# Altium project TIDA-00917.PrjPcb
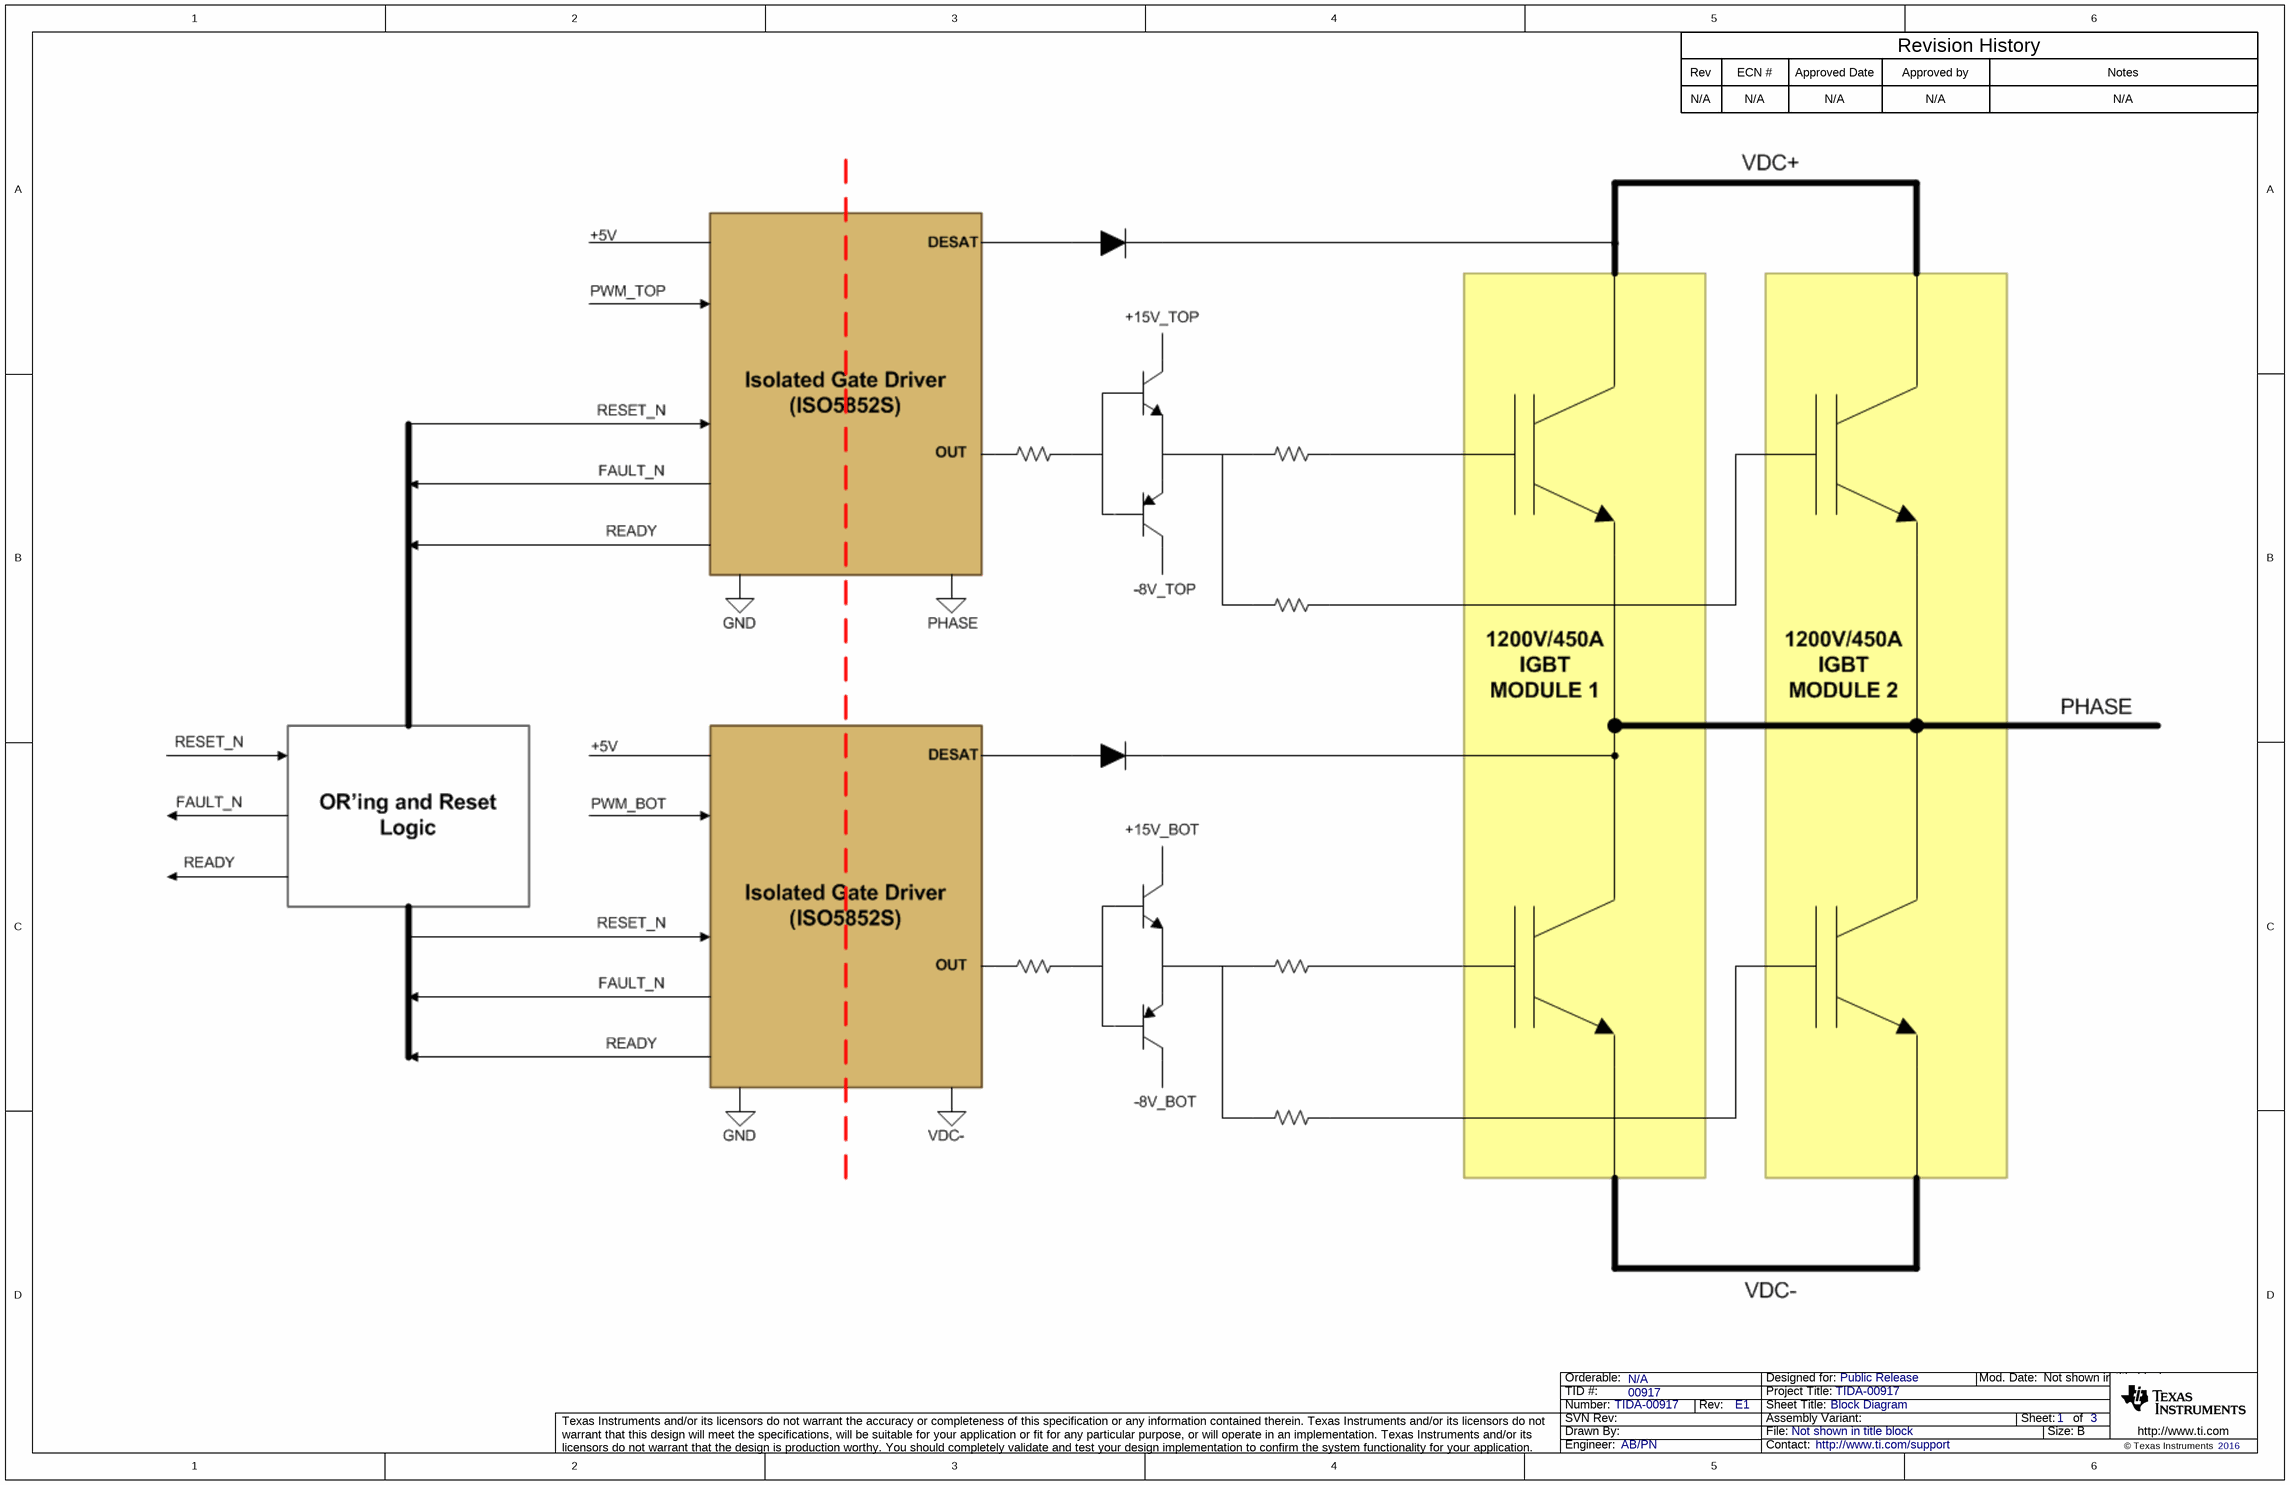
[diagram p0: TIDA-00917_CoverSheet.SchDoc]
TID: 00917; TechSupport: http://www.ti.com/support; SCH_Rev: E1; PRJ_Title: TIDA-00917; PRJ_Number: TIDA-00917; PRJ_Engineer: AB/PN; PRJ_Customer: Public Release; PCB_Rev: E1; PCB_Layout: Avinash N; EVM_orderable: N/A; CopyrightYear: 2016
3 sheets, 135 parts. Net scope: global (net labels, ports and power ports of the same name join across sheets).
Board file: TIDA-00917.PcbDoc
Sheets:
  TIDA-00917_CoverSheet.SchDoc
  TIDA-00917_BlankSheet.SchDoc
  TIDA-00917_EVM_Hardware.SchDoc

## Sheet TIDA-00917_CoverSheet.SchDoc: Block Diagram
size 431 x 279 mm; Date: Not shown in title block; ApprovedBy: Not shown in title block; CheckedBy: Not shown in title block; Author: Not shown in title block; CompanyName: Not shown in title block; Engineer: Not shown in title block; Organization: Not shown in title block; Address1: Not shown in title block; Address2: Not shown in title block; Address3: Not shown in title block; Address4: Not shown in title block; DocumentNumber: 1; Revision: Use project parameter SCH_Rev; SheetNumber: 1; SheetTotal: 3; PageSetup: Record=PageOptions¦CenterHorizontal=True¦CenterVertical=True¦PrintScale=1.00¦XCorrection=1.00¦YCorrection=1.00¦PrintKind=0¦BorderSize=5000000¦LeftOffset=0¦BottomOffset=0¦Orientation=2¦PaperLength=1000¦PaperWidth=1000¦Scale=100¦PaperSource=15¦PrintQuality=600¦MediaType=1¦DitherType=10¦PaperKind=Letter¦PrintScaleMode=1

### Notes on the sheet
- Rev
- N/A
- ECN #
- Approved Date
- Approved by
- Revision History
- Notes

## Sheet TIDA-00917_BlankSheet.SchDoc: IGBT Gate Drive
size 431 x 279 mm; Date: Not shown in title block; ApprovedBy: Not shown in title block; CheckedBy: Not shown in title block; Author: Not shown in title block; CompanyName: Not shown in title block; Engineer: Not shown in title block; Organization: Not shown in title block; Address1: Not shown in title block; Address2: Not shown in title block; Address3: Not shown in title block; Address4: Not shown in title block; DocumentNumber: 1; Revision: Use project parameter SCH_Rev; SheetNumber: 2; SheetTotal: 3; PageSetup: Record=PageOptions¦CenterHorizontal=True¦CenterVertical=True¦PrintScale=1.00¦XCorrection=1.00¦YCorrection=1.00¦PrintKind=0¦BorderSize=5000000¦LeftOffset=0¦BottomOffset=0¦Orientation=2¦PaperLength=1000¦PaperWidth=1000¦Scale=100¦PaperSource=15¦PrintQuality=600¦MediaType=1¦DitherType=10¦PrintScaleMode=1¦PaperKind=Letter
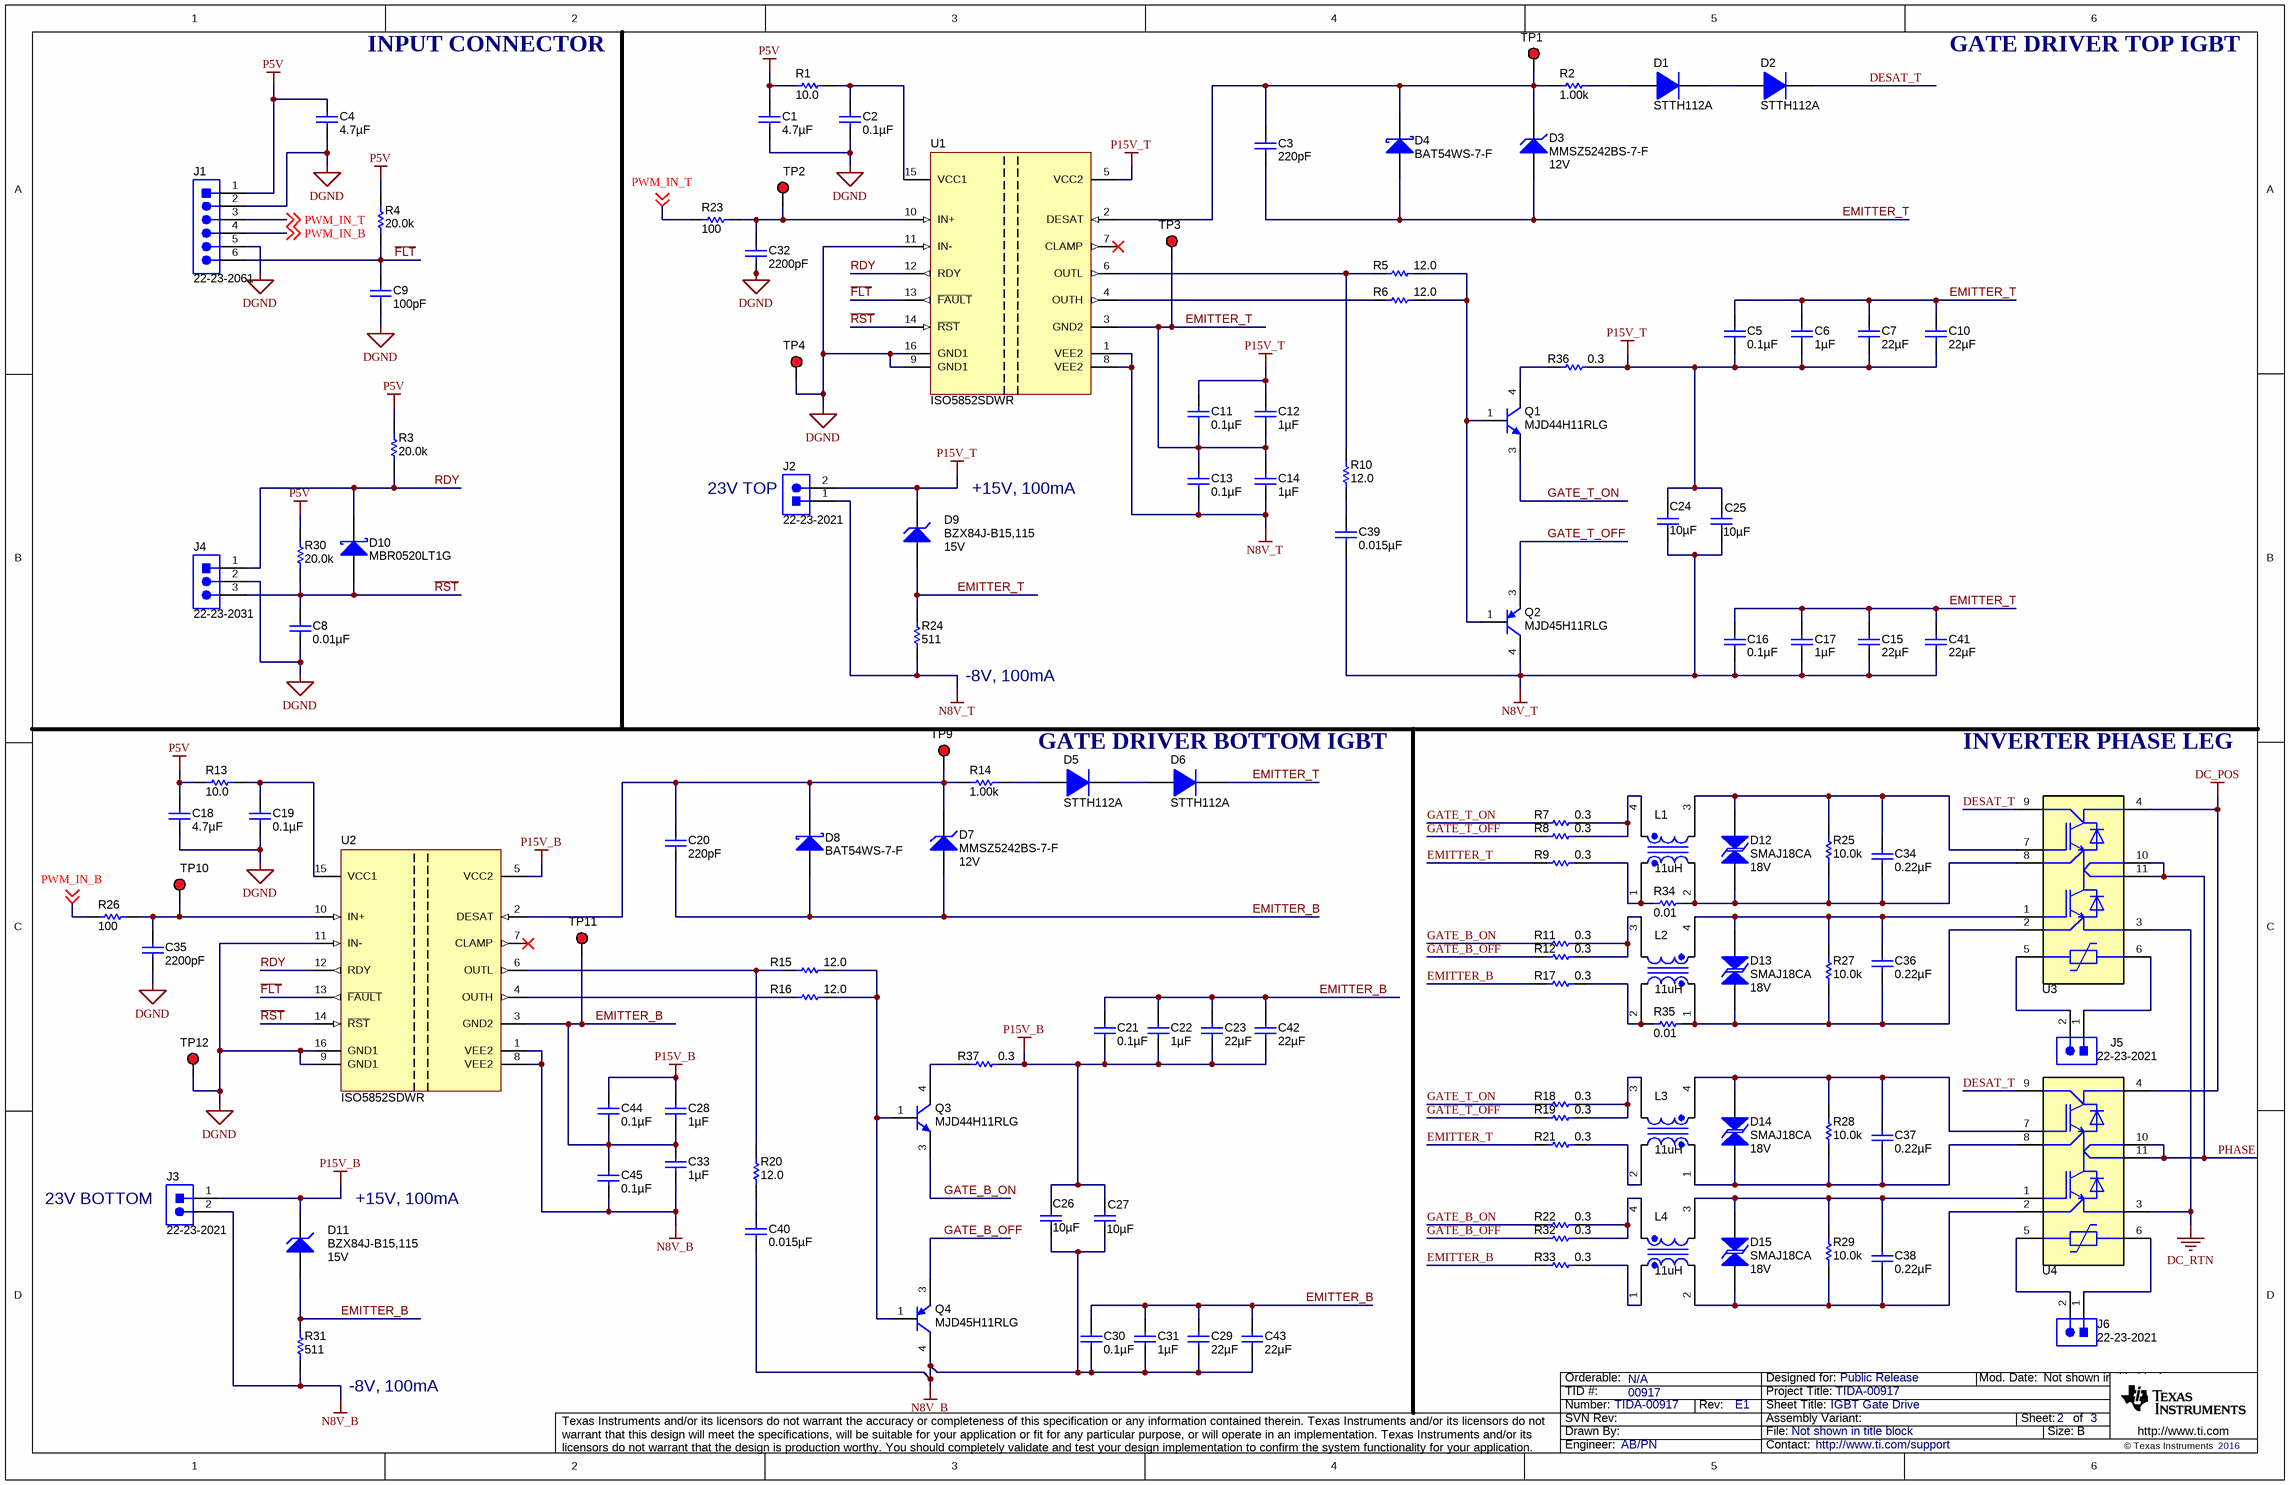
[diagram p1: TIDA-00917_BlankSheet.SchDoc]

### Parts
C1  ValueDisplayed: 4.7µF  [0805_HV]  (hidden comment: GRM21BR71C475KA73L)
C2  ValueDisplayed: 0.1µF  [0603]  (hidden comment: C1608X7R1H104K080AA)
C3  ValueDisplayed: 220pF  [0603]  (hidden comment: C0603C221K5RACTU)
C4  ValueDisplayed: 4.7µF  [0805_HV]  (hidden comment: GRM21BR71C475KA73L)
C5  ValueDisplayed: 0.1µF  [0603]  (hidden comment: C1608X7R1H104K080AA)
C6  ValueDisplayed: 1µF  [0805_HV]  (hidden comment: CL21B105KBFNNNE)
C7  ValueDisplayed: 22µF  [1210_270]  (hidden comment: GRM32ER71E226KE15L)
C8  ValueDisplayed: 0.01µF  [0402]  (hidden comment: GRM155R71C103KA01D)
C9  ValueDisplayed: 100pF  [0402]  (hidden comment: C0402C101J3GACTU)
C10  ValueDisplayed: 22µF  [1210_270]  (hidden comment: GRM32ER71E226KE15L)
C11  ValueDisplayed: 0.1µF  [0603]  (hidden comment: C1608X7R1H104K080AA)
C12  ValueDisplayed: 1µF  [1206]  (hidden comment: C3216X7R2A105M160AA)
C13  ValueDisplayed: 0.1µF  [0603]  (hidden comment: C1608X7R1H104K080AA)
C14  ValueDisplayed: 1µF  [1206]  (hidden comment: C3216X7R2A105M160AA)
C15  ValueDisplayed: 22µF  [1210_270]  (hidden comment: GRM32ER71E226KE15L)
C16  ValueDisplayed: 0.1µF  [0603]  (hidden comment: C1608X7R1H104K080AA)
C17  ValueDisplayed: 1µF  [0805_HV]  (hidden comment: CL21B105KBFNNNE)
C18  ValueDisplayed: 4.7µF  [0805_HV]  (hidden comment: GRM21BR71C475KA73L)
C19  ValueDisplayed: 0.1µF  [0603]  (hidden comment: C1608X7R1H104K080AA)
C20  ValueDisplayed: 220pF  [0603]  (hidden comment: C0603C221K5RACTU)
C21  ValueDisplayed: 0.1µF  [0603]  (hidden comment: C1608X7R1H104K080AA)
C22  ValueDisplayed: 1µF  [0805_HV]  (hidden comment: CL21B105KBFNNNE)
C23  ValueDisplayed: 22µF  [1210_270]  (hidden comment: GRM32ER71E226KE15L)
C24  ValueDisplayed: 10µF  [1210_280]  (hidden comment: UMK325AB7106KM-T)
C25  ValueDisplayed: 10µF  [1210_280]  (hidden comment: UMK325AB7106KM-T)
C26  ValueDisplayed: 10µF  [1210_280]  (hidden comment: UMK325AB7106KM-T)
C27  ValueDisplayed: 10µF  [1210_280]  (hidden comment: UMK325AB7106KM-T)
C28  ValueDisplayed: 1µF  [1206]  (hidden comment: C3216X7R2A105M160AA)
C29  ValueDisplayed: 22µF  [1210_270]  (hidden comment: GRM32ER71E226KE15L)
C30  ValueDisplayed: 0.1µF  [0603]  (hidden comment: C1608X7R1H104K080AA)
C31  ValueDisplayed: 1µF  [0805_HV]  (hidden comment: CL21B105KBFNNNE)
C32  ValueDisplayed: 2200pF  [0402]  (hidden comment: 885012205027)
C33  ValueDisplayed: 1µF  [1206]  (hidden comment: C3216X7R2A105M160AA)
C34  ValueDisplayed: 0.22µF  [0603]  (hidden comment: GRM188R71H224KAC4D)
C35  ValueDisplayed: 2200pF  [0402]  (hidden comment: 885012205027)
C36  ValueDisplayed: 0.22µF  [0603]  (hidden comment: GRM188R71H224KAC4D)
C37  ValueDisplayed: 0.22µF  [0603]  (hidden comment: GRM188R71H224KAC4D)
C38  ValueDisplayed: 0.22µF  [0603]  (hidden comment: GRM188R71H224KAC4D)
C39  ValueDisplayed: 0.015µF  [0603]  (hidden comment: C0603C153K1RACTU)
C40  ValueDisplayed: 0.015µF  [0603]  (hidden comment: C0603C153K1RACTU)
C41  ValueDisplayed: 22µF  [1210_270]  (hidden comment: GRM32ER71E226KE15L)
C42  ValueDisplayed: 22µF  [1210_270]  (hidden comment: GRM32ER71E226KE15L)
C43  ValueDisplayed: 22µF  [1210_270]  (hidden comment: GRM32ER71E226KE15L)
C44  ValueDisplayed: 0.1µF  [0603]  (hidden comment: C1608X7R1H104K080AA)
C45  ValueDisplayed: 0.1µF  [0603]  (hidden comment: C1608X7R1H104K080AA)
D1  STTH112A  [SMA]
D2  STTH112A  [SMA]
D3  MMSZ5242BS-7-F  value 12V  [sod-323]
D4  BAT54WS-7-F  [SOD-323]
D5  STTH112A  [SMA]
D6  STTH112A  [SMA]
D7  MMSZ5242BS-7-F  value 12V  [sod-323]
D8  BAT54WS-7-F  [SOD-323]
D9  BZX84J-B15,115  Voltage - Zener (Nom) (Vz): 15V  [SOD-323F]
D10  MBR0520LT1G  [SOD-123]
D11  BZX84J-B15,115  Voltage - Zener (Nom) (Vz): 15V  [SOD-323F]
D12  SMAJ18CA  value 18V  [SMA]
D13  SMAJ18CA  value 18V  [SMA]
D14  SMAJ18CA  value 18V  [SMA]
D15  SMAJ18CA  value 18V  [SMA]
J1  22-23-2061  [Molex_22-23-2061]
J2  22-23-2021  [Molex_22-23-2021]
J3  22-23-2021  [Molex_22-23-2021]
J4  22-23-2031  [Molex_22-23-2031]
J5  22-23-2021  [Molex_22-23-2021]
J6  22-23-2021  [Molex_22-23-2021]
L1  value 11uH  [SIMDAD_1812]  (hidden comment: B82789C0113N002)
L2  value 11uH  [SIMDAD_1812]  (hidden comment: B82789C0113N002)
L3  value 11uH  [SIMDAD_1812]  (hidden comment: B82789C0113N002)
L4  value 11uH  [SIMDAD_1812]  (hidden comment: B82789C0113N002)
Q1  MJD44H11RLG  [DPAK]
Q2  MJD45H11RLG  [DPAK]
Q3  MJD44H11RLG  [DPAK]
Q4  MJD45H11RLG  [DPAK]
R1  ValueDisplayed: 10.0  [0603]  (hidden comment: CRCW060310R0FKEA)
R2  ValueDisplayed: 1.00k  [0805_HV]  (hidden comment: ERJ-6ENF1001V)
R3  ValueDisplayed: 20.0k  [0402]  (hidden comment: CRCW040220K0FKED)
R4  ValueDisplayed: 20.0k  [0402]  (hidden comment: CRCW040220K0FKED)
R5  ValueDisplayed: 12.0  [1206]  (hidden comment: RC1206FR-0712RL)
R6  ValueDisplayed: 12.0  [1206]  (hidden comment: RC1206FR-0712RL)
R7  ValueDisplayed: 0.3  [2512]  (hidden comment: CSRN2512FKR300)
R8  ValueDisplayed: 0.3  [2512]  (hidden comment: CSRN2512FKR300)
R9  ValueDisplayed: 0.3  [2512]  (hidden comment: CSRN2512FKR300)
R10  ValueDisplayed: 12.0  [1206]  (hidden comment: RC1206FR-0712RL)
R11  ValueDisplayed: 0.3  [2512]  (hidden comment: CSRN2512FKR300)
R12  ValueDisplayed: 0.3  [2512]  (hidden comment: CSRN2512FKR300)
R13  ValueDisplayed: 10.0  [0603]  (hidden comment: CRCW060310R0FKEA)
R14  ValueDisplayed: 1.00k  [0805_HV]  (hidden comment: ERJ-6ENF1001V)
R15  ValueDisplayed: 12.0  [1206]  (hidden comment: RC1206FR-0712RL)
R16  ValueDisplayed: 12.0  [1206]  (hidden comment: RC1206FR-0712RL)
R17  ValueDisplayed: 0.3  [2512]  (hidden comment: CSRN2512FKR300)
R18  ValueDisplayed: 0.3  [2512]  (hidden comment: CSRN2512FKR300)
R19  ValueDisplayed: 0.3  [2512]  (hidden comment: CSRN2512FKR300)
R20  ValueDisplayed: 12.0  [1206]  (hidden comment: RC1206FR-0712RL)
R21  ValueDisplayed: 0.3  [2512]  (hidden comment: CSRN2512FKR300)
R22  ValueDisplayed: 0.3  [2512]  (hidden comment: CSRN2512FKR300)
R23  ValueDisplayed: 100  [0402]  (hidden comment: CRCW0402100RFKED)
R24  ValueDisplayed: 511  [1206]  (hidden comment: ERJ-8ENF5110V)
R25  ValueDisplayed: 10.0k  [0603]  (hidden comment: ERJ-3EKF1002V)
R26  ValueDisplayed: 100  [0402]  (hidden comment: CRCW0402100RFKED)
R27  ValueDisplayed: 10.0k  [0603]  (hidden comment: ERJ-3EKF1002V)
R28  ValueDisplayed: 10.0k  [0603]  (hidden comment: ERJ-3EKF1002V)
R29  ValueDisplayed: 10.0k  [0603]  (hidden comment: ERJ-3EKF1002V)
R30  ValueDisplayed: 20.0k  [0402]  (hidden comment: CRCW040220K0FKED)
R31  ValueDisplayed: 511  [1206]  (hidden comment: ERJ-8ENF5110V)
R32  ValueDisplayed: 0.3  [2512]  (hidden comment: CSRN2512FKR300)
R33  ValueDisplayed: 0.3  [2512]  (hidden comment: CSRN2512FKR300)
R34  ValueDisplayed: 0.01  [1206]  (hidden comment: WSLP1206R0100FEA)
R35  ValueDisplayed: 0.01  [1206]  (hidden comment: WSLP1206R0100FEA)
R36  ValueDisplayed: 0.3  [2512]  (hidden comment: CSRN2512FKR300)
R37  ValueDisplayed: 0.3  [2512]  (hidden comment: CSRN2512FKR300)
TP1  5005  [Keystone5005]  (value not drawn)
TP2  5005  [Keystone5005]  (value not drawn)
TP3  5005  [Keystone5005]  (value not drawn)
TP4  5005  [Keystone5005]  (value not drawn)
TP9  5005  [Keystone5005]  (value not drawn)
TP10  5005  [Keystone5005]  (value not drawn)
TP11  5005  [Keystone5005]  (value not drawn)
TP12  5005  [Keystone5005]  (value not drawn)
U1  ISO5852SDWR  [DW0016B_HV]
U2  ISO5852SDWR  [DW0016B_HV]
U3  SEMIX453GB12E4P  [SEMIKRON_SEMIX453GB12E4P]  (value not drawn)
U4  SEMIX453GB12E4P  [SEMIKRON_SEMIX453GB12E4P]  (value not drawn)

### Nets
DC_POS: U3.4 U4.4
DC_RTN: U3.3 U4.3
DGND: C1.2 C2.2 C4.2 C8.2 C9.2 C18.2 C19.2 C32.2 C35.2 J1.2 J1.5 J4.2 TP4.1 TP12.1 U1.9(GND1) U1.11(IN-) U1.16(GND1) U2.9(GND1) U2.11(IN-) U2.16(GND1)
N8V_B: C26.2 C27.2 C29.2 C30.2 C31.2 C33.2 C40.2 C43.2 C45.2 J3.2 Q4.4(C) R31.1 U2.1(VEE2) U2.8(VEE2)
N8V_T: C13.2 C14.2 C15.2 C16.2 C17.2 C24.2 C25.2 C39.2 C41.2 J2.1 Q2.4(C) R24.1 U1.1(VEE2) U1.8(VEE2)
P5V: C1.1 C4.1 C18.1 J1.1 R1.1 R3.2 R4.2 R13.1 R30.2
P15V_B: C21.2 C22.2 C23.2 C26.1 C27.1 C28.1 C42.2 C44.1 D11.1(K) J3.1 R37.2 U2.5(VCC2)
P15V_T: C5.2 C6.2 C7.2 C10.2 C11.1 C12.1 C24.1 C25.1 D9.1(K) J2.2 R36.2 U1.5(VCC2)
~{FLT}: C9.1 J1.6 R4.1 U1.13(~{FAULT}) U2.13(~{FAULT})
~{RST}: C8.1 D10.2(A) J4.3 R30.1 U1.14(~{RST}) U2.14(~{RST})
DESAT_T: D2.1(K) U3.9 U4.9
EMITTER_B: C20.2 C21.1 C22.1 C23.1 C28.2 C29.1 C30.1 C31.1 C33.1 C42.1 C43.1 C44.2 C45.1 D7.2(A) D8.2(A) D11.2(A) R17.1 R31.2 R33.1 TP11.1 U2.3(GND2)
EMITTER_T: C3.2 C5.1 C6.1 C7.1 C10.1 C11.2 C12.2 C13.1 C14.1 C15.1 C16.1 C17.1 C41.1 D3.2(A) D4.2(A) D6.1(K) D9.2(A) R9.1 R21.1 R24.2 TP3.1 U1.3(GND2)
GATE_B_OFF: Q4.3(E) R12.1 R32.1
GATE_B_ON: Q3.3(E) R11.1 R22.1
GATE_T_OFF: Q2.3(E) R8.1 R19.1
GATE_T_ON: Q1.3(E) R7.1 R18.1
PHASE: U3.10 U3.11 U4.10 U4.11
PWM_IN_B: J1.4 R26.1 ; off-sheet PWM_IN_B
PWM_IN_T: J1.3 R23.1 ; off-sheet PWM_IN_T
RDY: D10.1(K) J4.1 R3.1 U1.12(RDY) U2.12(RDY)
NetC2_1: C2.1 R1.2 U1.15(VCC1)
NetC3_1: C3.1 D3.1(K) D4.1(K) R2.1 TP1.1 U1.2(DESAT)
NetC19_1: C19.1 R13.2 U2.15(VCC1)
NetC20_1: C20.1 D7.1(K) D8.1(K) R14.1 TP9.1 U2.2(DESAT)
NetC32_1: C32.1 R23.2 TP2.1 U1.10(IN+)
NetC34_1: C34.1 D12.2 L1.3 R25.2 U3.7
NetC34_2: C34.2 D12.1 L1.2 R25.1 R34.2 U3.8
NetC35_1: C35.1 R26.2 TP10.1 U2.10(IN+)
NetC36_1: C36.1 D13.2 L2.4 R27.2 U3.1
NetC36_2: C36.2 D13.1 L2.1 R27.1 R35.2 U3.2
NetC37_1: C37.1 D14.2 L3.4 R28.2 U4.7
NetC37_2: C37.2 D14.1 L3.1 R28.1 U4.8
NetC38_1: C38.1 D15.2 L4.3 R29.2 U4.1
NetC38_2: C38.2 D15.1 L4.2 R29.1 U4.2
NetC39_1: C39.1 R10.1
NetC40_1: C40.1 R20.1
NetD1_1: D1.1(K) D2.2(A)
NetD1_2: D1.2(A) R2.2
NetD5_1: D5.1(K) D6.2(A)
NetD5_2: D5.2(A) R14.2
NetJ5_1: J5.1 U3.6
NetJ5_2: J5.2 U3.5
NetJ6_1: J6.1 U4.6
NetJ6_2: J6.2 U4.5
NetL1_1: L1.1 R9.2 R34.1
NetL1_4: L1.4 R7.2 R8.2
NetL2_2: L2.2 R17.2 R35.1
NetL2_3: L2.3 R11.2 R12.2
NetL3_2: L3.2 R21.2
NetL3_3: L3.3 R18.2 R19.2
NetL4_1: L4.1 R33.2
NetL4_4: L4.4 R22.2 R32.2
NetQ1_1: Q1.1(B) Q2.1(B) R5.2 R6.2
NetQ1_4: Q1.4(C) R36.1
NetQ3_1: Q3.1(B) Q4.1(B) R15.2 R16.2
NetQ3_4: Q3.4(C) R37.1
NetR5_1: R5.1 R10.2 U1.6(OUTL)
NetR6_1: R6.1 U1.4(OUTH)
NetR15_1: R15.1 R20.2 U2.6(OUTL)
NetR16_1: R16.1 U2.4(OUTH)

Not connected (* = marked no-connect by the designer): U1 7(CLAMP)*; U2 7(CLAMP)*

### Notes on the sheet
- INPUT CONNECTOR
- GATE DRIVER TOP IGBT
- (near J2) 23V TOP
- +15V, 100mA
- -8V, 100mA
- GATE DRIVER BOTTOM IGBT
- INVERTER PHASE LEG
- (near J3) 23V BOTTOM

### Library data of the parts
C1 C4 C18 = GRM21BR71C475KA73L: CAP, CERM, 4.7 µF, 16 V, +/- 10%, X7R, 0805; Manufacturer: MuRata; Polarized: N; CompType: Capacitor; Value: 4.7uF; U/M: EA; Cap_F: 0.0000047; Tolerance_%: 10; ESR_ohm: 0.006; Value1: 0.006 ohm; VDC_V: 16; Value2: 16V; TaMin_C: -55; TaMax_C: 125; Cap_Case: 0805; SizeArea_mm2: 2.5; SizeAreaWB_mm2: 6.75; SizeX_mm: 2; SizeY_mm: 1.25; SizeZ_mm: 1.45; AEC Category: Q200
C2 C5 C16 C19 C21 C30 = C1608X7R1H104K080AA: CAP, CERM, 0.1 µF, 50 V, +/- 10%, X7R, 0603; Manufacturer: TDK; Polarized: N; CompType: Capacitor; Value: 0.1uF; U/M: EA; Cap_F: 0.0000001; Tolerance_%: 10; Value1: Unknown; VDC_V: 50; Value2: 50V; TaMin_C: -55; TaMax_C: 125; AEC Category: Q200
C3 C20 = C0603C221K5RACTU: CAP, CERM, 220 pF, 50 V, +/- 10%, X7R, 0603; Manufacturer: Kemet; Polarized: N; CompType: Capacitor; Value: 220pF; U/M: EA; Cap_F: 0.00000000022; Tolerance_%: 10; Value1: Unknown; VDC_V: 50; Value2: 50V; TaMin_C: -55; TaMax_C: 125; AEC Category: Q200
C6 C17 C22 C31 = CL21B105KBFNNNE: CAP, CERM, 1 µF, 50 V, +/- 10%, X7R, 0805; Manufacturer: Samsung Electro-Mechanics; Polarized: N; CompType: Capacitor; Value: 1uF; U/M: EA; Cap_F: 0.000001; Tolerance_%: 10; Value1: Unknown; VDC_V: 50; Value2: 50V; TaMin_C: -55; TaMax_C: 125; Cap_Case: 0805; AEC Category: Q200
C7 C10 C15 C23 C29 C41-C43 = GRM32ER71E226KE15L: CAP, CERM, 22 µF, 25 V, +/- 10%, X7R, 1210; Manufacturer: MuRata; Polarized: N; CompType: Capacitor; Value: 22uF; U/M: EA; Cap_F: 0.000022; Tolerance_%: 10; Value1: Unknown; VDC_V: 25; Value2: 25V; TaMin_C: -55; TaMax_C: 125; Cap_Case: 1210; SizeArea_mm2: 8; SizeAreaWB_mm2: 14.7; SizeX_mm: 3.2; SizeY_mm: 2.5; SizeZ_mm: 2.7; AEC Category: Q200
C8 = GRM155R71C103KA01D: CAP, CERM, 0.01 µF, 16 V, +/- 10%, X7R, 0402; Manufacturer: MuRata; Polarized: N; CompType: Capacitor; Value: 0.01uF; U/M: EA; Cap_F: 0.00000001; Tolerance_%: 10; Value1: Unknown; VDC_V: 16; Value2: 16V; TaMin_C: -55; TaMax_C: 125; SizeArea_mm2: 0.5; SizeAreaWB_mm2: 3; SizeX_mm: 1; SizeZ_mm: 0.6; AEC Category: Q200
C9 = C0402C101J3GACTU: CAP, CERM, 100 pF, 25 V, +/- 5%, C0G/NP0, 0402; Manufacturer: Kemet; Polarized: N; CompType: Capacitor; Value: 100pF; U/M: EA; Cap_F: 0.0000000001; Tolerance_%: 5; Value1: Unknown; VDC_V: 25; Value2: 25V; TaMin_C: -55; TaMax_C: 125; SizeArea_mm2: 0.5; SizeAreaWB_mm2: 3; SizeX_mm: 1; SizeZ_mm: 0.6; AEC Category: Q200
C11 C13 C44 C45 = C1608X7R1H104K080AA: CAP, CERM, 0.1 µF, 50 V, +/- 10%, X7R, 0603; Manufacturer: TDK; Polarized: N; CompType: Capacitor; Value: 0.1uF; U/M: EA; Cap_F: 0.0000001; Tolerance_%: 10; ESR_ohm: 0.0296; Value1: 0.0296 ohm; VDC_V: 50; Value2: 50V; IRMS_A: 0.97199; TaMin_C: -55; TaMax_C: 125; SizeArea_mm2: 1.28; SizeAreaWB_mm2: 4.68; SizeX_mm: 1.6; SizeY_mm: 0.8; SizeZ_mm: 1; AEC Category: Q200
C12 C14 C28 C33 = C3216X7R2A105M160AA: CAP, CERM, 1 µF, 100 V, +/- 20%, X7R, 1206; Manufacturer: TDK; Polarized: N; CompType: Capacitor; Value: 1uF; U/M: EA; Cap_F: 0.000001; Tolerance_%: 20; Value1: Unknown; VDC_V: 100; Value2: 100V; TaMin_C: -55; TaMax_C: 125; SizeArea_mm2: 5.12; SizeAreaWB_mm2: 10.92; SizeX_mm: 3.2; SizeY_mm: 1.6; SizeZ_mm: 1.35; AEC Category: Q200
C24-C27 = UMK325AB7106KM-T: CAP, CERM, 10 µF, 50 V, +/- 10%, X7R, 1210; Manufacturer: Taiyo Yuden; Polarized: N; CompType: Capacitor; Value: 10uF; U/M: EA; Cap_F: 0.00001; Tolerance_%: 10; Value1: Unknown; VDC_V: 50; Value2: 50V; TaMin_C: -55; TaMax_C: 125; Cap_Case: 1210; SizeArea_mm2: 8; SizeAreaWB_mm2: 14.7; SizeX_mm: 3.2; SizeY_mm: 2.5; SizeZ_mm: 2.8; AEC Category: Q200
C32 C35 = 885012205027: CAP, CERM, 2200 pF, 16 V, +/- 10%, X7R, 0402; Manufacturer: Wurth Elektronik; Polarized: N; CompType: Capacitor; Value: 2200pF; U/M: EA; Cap_F: 0.0000000022; Tolerance_%: 10; Value1: Unknown; VDC_V: 16; Value2: 16V; TaMin_C: -55; TaMax_C: 125; SizeArea_mm2: 0.5; SizeAreaWB_mm2: 3; SizeX_mm: 1; SizeZ_mm: 0.6; AEC Category: Q200
C34 C36-C38 = GRM188R71H224KAC4D: CAP, CERM, 0.22 µF, 50 V, +/- 10%, X7R, 0603; Manufacturer: MuRata; Polarized: N; CompType: Capacitor; Value: 0.22uF; U/M: EA; Cap_F: 0.00000022; Tolerance_%: 10; Value1: Unknown; VDC_V: 50; Value2: 50V; TaMin_C: -55; TaMax_C: 125; SizeArea_mm2: 1.28; SizeAreaWB_mm2: 4.68; SizeX_mm: 1.6; SizeY_mm: 0.8; SizeZ_mm: 1; AEC Category: Q200
C39 C40 = C0603C153K1RACTU: CAP, CERM, 0.015 µF, 100 V, +/- 10%, X7R, 0603; Manufacturer: Kemet; Polarized: N; CompType: Capacitor; Value: 0.015uF; U/M: EA; Cap_F: 0.000000015; Tolerance_%: 10; Value1: Unknown; VDC_V: 100; Value2: 100V; TaMin_C: -55; TaMax_C: 125; SizeArea_mm2: 1.28; SizeAreaWB_mm2: 4.68; SizeX_mm: 1.6; SizeY_mm: 0.8; SizeZ_mm: 1; AEC Category: Q200
D1 D2 D5 D6 = STTH112A: Diode, Ultrafast, 1200 V, 1 A, SMA; Manufacturer: STMicroelectronics; U/M: EA; Vf_V: 1.9; Value: 1200V; Value1: 1A; Value2: 1.9V; Io_A: 1; Vr_V: 1200; TJmax_C: 175; SizeAreaWB_mm2: 37.3428; SizeArea_mm2: 16.3228; SizeX_mm: 5.59; SizeY_mm: 2.92; SizeZ_mm: 2.87; AEC Category: Q101; AEC Qualified: N
D3 D7 = MMSZ5242BS-7-F: Diode, Zener, 12 V, 200 mW, SOD-323; Manufacturer: Diodes Inc.; SymbolCreator: a0412235; U/M: EA; Power_W: 0.2; Vz_V: 12; Value1: 0.2W; RJA_CperW: 350; AEC Category: Q101
D4 D8 = BAT54WS-7-F: Diode, Schottky, 30 V, 0.2 A, SOD-323; Manufacturer: Diodes Inc.; U/M: EA; Vf_V: 0.7; Value: 30V; Value1: 0.2A; Value2: 0.7V; Io_A: 0.2; Vr_V: 30; TJmax_C: 125; SizeAreaWB_mm2: 8.695; SizeArea_mm2: 3.645; SizeX_mm: 2.7; SizeY_mm: 1.35; SizeZ_mm: 1; AEC Category: Q101
D9 D11 = BZX100A, 115: DIODE ZENER 15V 550MW SOD323F; Manufacturer: NXP Semiconductors; Tolerance_%: ±2%; Impedance (Max) (Zzt): 15 Ohm; Current - Reverse Leakage @ Vr: 50nA @ 10.5V; Value: 1.1V @ 100mA
D10 = MBR0520LT1G: Diode, Schottky, 20 V, 0.5 A, SOD-123; Manufacturer: ON Semiconductor; U/M: EA; Vf_V: 0.385; Value: 20V; Value1: 0.5A; Value2: 0.385V; Io_A: 0.5; Vr_V: 20; TJmax_C: 125; RJC_CperW: 150; SizeAreaWB_mm2: 13.095; SizeArea_mm2: 6.545; SizeX_mm: 3.85; SizeY_mm: 1.7; SizeZ_mm: 1.35; AEC Category: Q101
D12-D15 = SMAJ18CA: Diode, TVS, Bi, 18 V, 400 W, SMA; Manufacturer: Littelfuse; U/M: EA; Power_W: 400; Vr_V: 18; Value1: 400W; RJA_CperW: 120; SizeAreaWB_mm2: 37.3428; SizeArea_mm2: 16.3228; SizeX_mm: 5.59; SizeY_mm: 2.92; SizeZ_mm: 2.87; AEC Category: Q101
J1 = 22-23-2061: Header, 2.54 mm, 6x1, Tin, TH; Manufacturer: Molex; SymbolCreator: a0412235; Pitch_mm: 2.54; Gender: Male; Shrouded: N; Row_Count: 1
J2 J3 J5 J6 = 22-23-2021: Header, 2.54mm, 2x1, Vertical, TH; Manufacturer: Molex; SymbolCreator: a0412235
J4 = 22-23-2031: Header, 2.54 mm, 3x1, Tin, TH; Manufacturer: Molex; SymbolCreator: a0799628; Pitch_mm: 2.54; Gender: Male; Shrouded: N; Row_Count: 1
L1-L4 = B82789C0104H001: Coupled inductor, 11 µH, 0.3 A, 0.25 ohm, SMD; Manufacturer: TDK; SymbolCreator: a0412235; Ind_H: 11.0E-6; DCR_ohm: 0.25
Q1 Q3 = MJD44H11RLG, ON Semiconductor: Transistor, NPN, 80 V, 8 A, AEC-Q101, DPAK; CompType: BJT; PNP: 0; NPN: 1; Vceo_V: 80; Value: 80 V; IcRated_A: 8; Value1: 8 A; TaMin_C: -55; TaMax_C: 150; U/M: EA; AEC Category: Q101; AEC Qualified: Y
Q2 Q4 = MJD45H11RLG, ON Semiconductor: Transistor, PNP, 80 V, 8 A, DPAK; CompType: BJT; PNP: 1; NPN: 0; Vceo_V: 80; Value: 80 V; IcRated_A: 8; Value1: 8 A; TaMin_C: -55; TaMax_C: 150; U/M: EA; AEC Category: Q101
R1 R13 = CRCW060310R0FKEA: RES, 10.0, 1%, 0.1 W, 0603; Manufacturer: Vishay-Dale; CompType: Resistor; Value: 10.0; Res_ohm: 10; Value_Code: 10R0; Tolerance_%: 1; Power_W: 0.1; Value2: 0.1W; VDC_V: 75; TempCo: 100 ppm/C; EIA_Code: E96; U/M: EA; AEC Category: Q200
R2 R14 = ERJ-6ENF1001V: RES, 1.00 k, 1%, 0.125 W, 0805; Manufacturer: Panasonic; CompType: Resistor; Value: 1.00k; Res_ohm: 1000; Value_Code: 1k00; Tolerance_%: 1; Power_W: 0.125; Value2: 0.125W; TempCo: 100 ppm/C; EIA_Code: E96; U/M: EA; AEC Category: Q200
R3 R4 R30 = CRCW040220K0FKED: RES, 20.0 k, 1%, 0.063 W, 0402; Manufacturer: Vishay-Dale; CompType: Resistor; Value: 20.0k; Res_ohm: 20000; Value_Code: 20k0; Tolerance_%: 1; Power_W: 0.063; Value2: 0.063W; VDC_V: 50; TempCo: 100 ppm/C; SizeArea_mm2: 0.5; SizeZ_mm: 0.6; EIA_Code: E96; U/M: EA; AEC Category: Q200
R5 R6 R10 R15 R16 R20 = RC1206FR-0712RL: RES, 12.0, 1%, 0.25 W, 1206; Manufacturer: Yageo America; CompType: Resistor; Value: 12.0; Res_ohm: 12; Value_Code: 12R0; Tolerance_%: 1; Power_W: 0.25; Value2: 0.25W; VDC_V: 200; TempCo: 100 ppm/C; SizeArea_mm2: 5.12; SizeX_mm: 3.2; SizeY_mm: 1.6; SizeZ_mm: 1.35; U/M: EA; AEC Category: Q200
R7-R9 R11 R12 R17-R19 R21 R22 R32 R33 R36 R37 = CSRN2512FKR300: RES, 0.3, 1%, 2 W, 2512; Manufacturer: Stackpole Electronics Inc; CompType: Resistor; Value: 0.3; Value_Code: R300; Tolerance_%: 1; Power_W: 2; Value2: 2W; TempCo: 200 ppm/C; SizeArea_mm2: 20.16; SizeX_mm: 6.3; SizeY_mm: 3.2; SizeZ_mm: 0.71; EIA_Code: E96; U/M: EA; AEC Category: Q200
R23 R26 = CRCW0402100RFKED: RES, 100, 1%, 0.063 W, 0402; Manufacturer: Vishay-Dale; CompType: Resistor; Value: 100; Value_Code: 100R; Tolerance_%: 1; Power_W: 0.063; Value2: 0.063W; VDC_V: 50; TempCo: 100 ppm/C; SizeArea_mm2: 0.5; SizeZ_mm: 0.6; EIA_Code: E96; U/M: EA; AEC Category: Q200
R24 R31 = ERJ-8ENF5110V: RES, 511, 1%, 0.25 W, 1206; Manufacturer: Panasonic; CompType: Resistor; Value: 511; Value_Code: 511R; Tolerance_%: 1; Power_W: 0.25; Value2: 0.25W; VDC_V: 200; TempCo: 100 ppm/C; SizeArea_mm2: 5.12; SizeX_mm: 3.2; SizeY_mm: 1.6; SizeZ_mm: 1.35; EIA_Code: E96; U/M: EA; AEC Category: Q200
R25 R27-R29 = ERJ-3EKF1002V: RES, 10.0 k, 1%, 0.1 W, 0603; Manufacturer: Panasonic; CompType: Resistor; Value: 10.0k; Res_ohm: 10000; Value_Code: 10k0; Tolerance_%: 1; Power_W: 0.1; Value2: 0.1W; VDC_V: 75; TempCo: 100 ppm/C; SizeArea_mm2: 1.28; SizeX_mm: 1.6; SizeY_mm: 0.8; EIA_Code: E96; U/M: EA; AEC Category: Q200
R34 R35 = WSLP1206R0100FEA: RES, 0.01, 1%, 1 W, 1206; Manufacturer: Vishay-Dale; CompType: Resistor; Value: 0.01; Value_Code: R010; Tolerance_%: 1; Value2: 1W; TempCo: 75 ppm/C; SizeArea_mm2: 5.12; SizeX_mm: 3.2; SizeY_mm: 1.6; SizeZ_mm: 1.35; EIA_Code: E96; U/M: EA; AEC Category: Q200
TP1-TP4 TP9-TP12 = 5005: Test Point, Compact, Red, TH; Manufacturer: Keystone; CompType: Test Point Loop; ContactFinish: Silver
U1 U2 = ISO5852SDWR: 2.5 / 5 A Isolated IGBT Gate Driver with Split Outputs and Active Safety Features, DW0016A; Manufacturer: Texas Instruments; SymbolCreator: a0411947; CompType: IC; U/M: EA
U3 U4 = SEMIX453GB12E4P: IGBT Modules, SEMiX 3p, TH; Manufacturer: SEMIKRON; SymbolCreator: Altium

## Sheet TIDA-00917_EVM_Hardware.SchDoc: Hardware
size 431 x 279 mm; Date: Not shown in title block; ApprovedBy: Not shown in title block; CheckedBy: Not shown in title block; Author: Not shown in title block; CompanyName: Not shown in title block; Engineer: Not shown in title block; Organization: Not shown in title block; Address1: Not shown in title block; Address2: Not shown in title block; Address3: Not shown in title block; Address4: Not shown in title block; DocumentNumber: 1; Revision: Use project parameter SCH_Rev; SheetNumber: 3; SheetTotal: 3; PageSetup: Record=PageOptions¦CenterHorizontal=True¦CenterVertical=True¦PrintScale=1.00¦XCorrection=1.00¦YCorrection=1.00¦PrintKind=0¦BorderSize=5000000¦LeftOffset=0¦BottomOffset=0¦Orientation=2¦PaperLength=1000¦PaperWidth=1000¦Scale=100¦PaperSource=15¦PrintQuality=600¦MediaType=1¦DitherType=10¦PaperKind=Letter¦PrintScaleMode=1
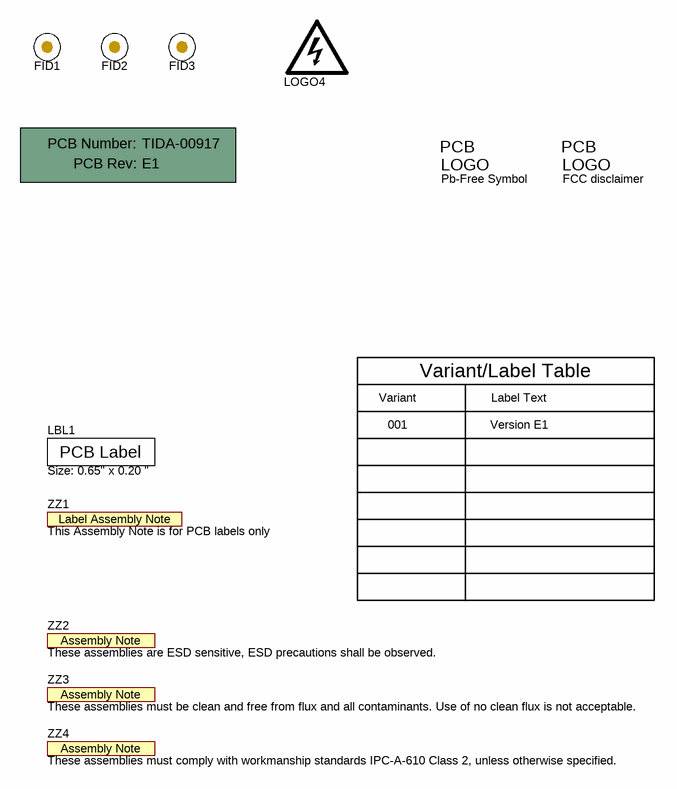
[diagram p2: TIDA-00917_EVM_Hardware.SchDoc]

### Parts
!PCB1  Printed Circuit Board  (value not drawn)  (mechanical)
FID1  Fiducial  [Fiducial10-20]  (value not drawn)
FID2  Fiducial  [Fiducial10-20]  (value not drawn)
FID3  Fiducial  [Fiducial10-20]  (value not drawn)
LBL1  Size: 0.65" x 0.20 "  [Label_650x200]
Logo2  Pb-Free Symbol  [Pb-Free_Overlay_Small]  (no BOM)
Logo3  FCC disclaimer  [FCC_disclaimer]  (no BOM)
LOGO4  DANGER HIGH VOLTAGE  [IEC_HighVoltage_medium]  (value not drawn)  (no BOM)
ZZ1  This Assembly Note is for PCB labels only  [AssemblyNoteLabel]  (no BOM)
ZZ2  These assemblies are ESD sensitive, ESD precautions shall be observed.  [AssemblyNote]  (no BOM)
ZZ3  These assemblies must be clean and free from flux and all contaminants. Use of no clean flux is not acceptable.  [AssemblyNote]  (no BOM)
ZZ4  These assemblies must comply with workmanship standards IPC-A-610 Class 2, unless otherwise specified.  [AssemblyNote]  (no BOM)

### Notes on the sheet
- Variant
- Variant/Label Table
- Label Text
- 001
- Version E1

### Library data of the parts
!PCB1 = PCB: Manufacturer: Any; PartNumber: TIDA-00917; SymbolCreator: a0412235
FID1-FID3 = Fiducial: Fiducial mark.  There is nothing to buy or mount.; SymbolCreator: codlsc
LBL1 = THT-14-423-10: Thermal Transfer Printable Labels, 0.650" W x 0.200" H - 10,000 per roll; Manufacturer: Brady; SymbolCreator: a0412235; CompType: Label
Logo2 = Pb-Free: SymbolCreator: a0412235
Logo3 = FCC_disclaimer: SymbolCreator: codlsc
LOGO4 = IEC_HighVoltage: IEC 61010-1 High Voltage Warning; SymbolCreator: a0412235
ZZ1 = AssemblyNoteLabel: SymbolCreator: a0412235
ZZ2-ZZ4 = AssemblyNote: SymbolCreator: codlsc

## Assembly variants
001: not fitted FID1 FID2 FID3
